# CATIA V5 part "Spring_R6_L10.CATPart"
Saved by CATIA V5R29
Part number: Spring_R6_L10
Definition: Cadenas PARTsolutions
Source: Unknown
Description: Economy Torsion Spring
Bounding box of the stored display mesh (mm): x -196 to 70, y -33.2 to 33.2, z -45.65 to 4.15
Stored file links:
  C:\Users\Administrator\Desktop\프로젝트\Boxfold\TapeCutter\Spring_R6_L10.CATPart
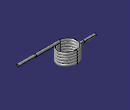
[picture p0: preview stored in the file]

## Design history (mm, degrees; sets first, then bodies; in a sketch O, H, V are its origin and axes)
Body1 "C-UA180R6-5-1.0-C-LC10-RC10" (main body)
  Solid1: solid without history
